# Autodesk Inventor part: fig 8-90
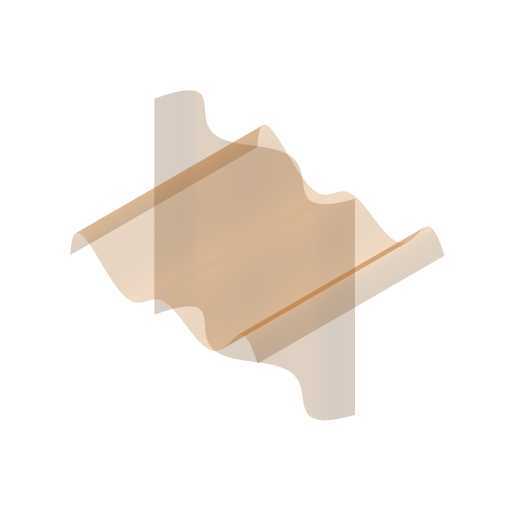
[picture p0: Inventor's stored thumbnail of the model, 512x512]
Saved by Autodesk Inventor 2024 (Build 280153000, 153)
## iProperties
Shininess: 64.0
Length Units: 11269
Angle Units: 11279
Time Units: 11290
Mass Units: 11283
Length Display Precision: 3
Angle Display Precision: 2
Compacted: True
Part Number: fig 8-90
Document SubType Name: Modeling
Created: 2003-08
Designer: Owner
Manufacturer: Standard
Standards Organization: Custom
Density: 1 g/cm^3
Material: Generic
Appearance: Default
Density: 0.0
Volumn: 0.0
Area: 0.0
PropertySet Name: Model Information
Control State: 0
Master: False
Checked Out: False
Author: Owner
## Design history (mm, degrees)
sketch "Sketch1"
  geometry: 7 further points
  constraints: 7 other
  dimensions: "d0" = 80 horizontal distance of point (40, 1.742) point (-40, -4.065); "d1" = 40 horizontal distance of point (0, 0) point (-40, -4.065)
extrude_surface "ExtrusionSrf1" sketch "Sketch1" dims "d2" = 80, "d3" = 0
sketch "Sketch2"
  geometry: L1 (40, 0)-(40, -40) reference; L2 (-40, 0)-(-40, -40) reference; 7 further points
  constraints: 2 point on line, 7 other
extrude_surface "ExtrusionSrf2" sketch "Sketch2" dims "d4" = 80, "d5" = 0
sketch "Sketch4"
  geometry: L1 (52.956, 12.425)-(-10.974, 12.425); A1 r 27.841 centre (-10.974, -15.416) between (-10.974, 12.425) and (-7.259, -43.008)
  constraints: 2 end point, 2 point on circle, 1 centre point, 1 horizontal, 1 tangent
sketch "Sketch3"
  geometry: 2 further points
  constraints: 4 other
body "Srf1"
body "Srf2"
